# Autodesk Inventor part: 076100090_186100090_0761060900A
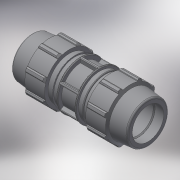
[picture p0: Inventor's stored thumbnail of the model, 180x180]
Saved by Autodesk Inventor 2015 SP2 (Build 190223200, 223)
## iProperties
Created: 2017-02
Part Number: 076100090_186100090_0761060900A
Material: Generic
Description: PLASSON REPAIR COUPLER 90
Document SubType Name: Modeling
Designer: KIM
Mass: 2528.64 g
Surface Area: 2854.29 cm^2
Volume: 2528.64 cm^3
Density: 1 g/cm^3
Appearance: Default
Author: KIM
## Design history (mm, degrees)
derived "07610.ipt"
feature "Solid1::07610.ipt"
tag "TaggingFeature1"
body "Solid1"
other parameters: "d1" = 335, "d4" = 27.91667, "d5" = 47.85714, "d7" = 154, "d8" = 115.5, "d9" = 47.85714, "d11" = 3.48571, "d12" = 123.2, "d13" = 120 deg, "d14" = 126, "d15" = 6 deg, "d16" = 138.6, "d18" = 4.5, "d19" = 35 deg, "d20" = 17.5 deg, "d21" = 143.22, "d23" = 0, "d25" = 360 deg, "d27" = 3.08, "d33" = 1.8, "d34" = 7.7, "d36" = 0, "d37" = 1.8, "d38" = 1.8, "d40" = 360 deg, "d42" = 60.3, "d43" = 4.62, "d46" = 2.7, "d50" = 13.57143, "d51" = 123.2, "E_" = 154, "H_" = 335, "l_" = 168, "d49" = 30.62857
